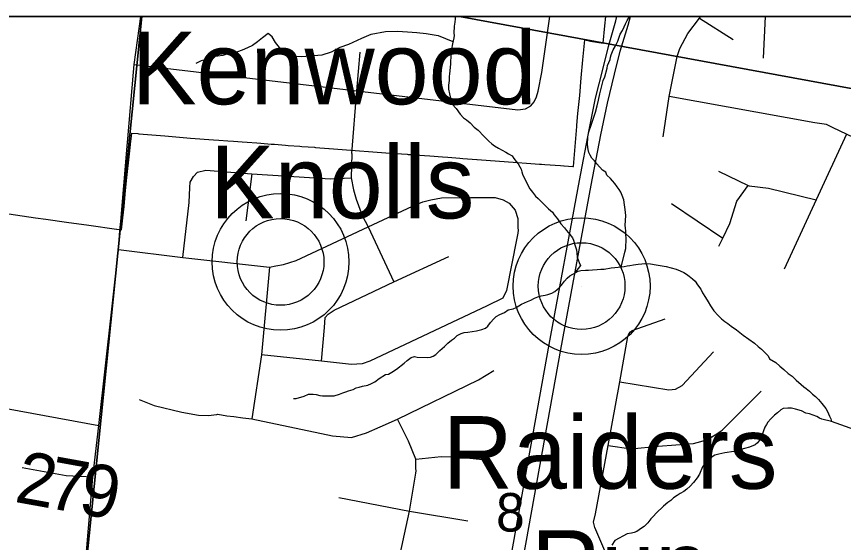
# Model space of a CAD drawing. Extents: x 0 to 34, y 0 to 22.
# Drawn here: x 3.9828 to 4.4325, y 20.6139 to 20.9 of the extents above; entities that cross this region are included whole.
import ezdxf

# ---------------------------------------------------------------- set-up
doc = ezdxf.new("R2010")
doc.units = 0
for name, color, linetype in [('GM_X_City_Street', 7, 'Continuous'), ('GM_X_Corporation', 7, 'Continuous'), ('GM_X_County_Road', 7, 'Continuous'), ('GM_X_County_Road_Text', 7, 'Continuous'), ('GM_X_Interstate_Route', 7, 'Continuous'), ('GM_X_Minor_River', 7, 'Continuous'), ('GM_X_Section_Text', 7, 'Continuous'), ('GM_X_State_Shield', 7, 'Continuous'), ('GM_X_Township_Road', 7, 'Continuous'), ('GM_X_Unincorporated', 7, 'Continuous'), ('GM_X_Unincorporated_Location', 7, 'Continuous'), ('GM_X_Unincorporated_Text', 7, 'Continuous'), ('SH_Cut_Line', 7, 'Continuous'), ('SH_Data', 7, 'Continuous')]:
    doc.layers.add(name, color=color, linetype=linetype)

msp = doc.modelspace()

# ---------------------------------------------------------------- linework, layer by layer
at = {"layer": 'GM_X_City_Street'}
for points in [[(3.97497, 20.79311), (3.9931, 20.79045), (3.99873, 20.78971), (4.01, 20.78813), (4.0222, 20.78643), (4.03714, 20.78434), (4.03742, 20.78431), (4.03996, 20.78396), (4.04066, 20.79041), (4.04135, 20.79658), (4.04194, 20.80341), (4.04288, 20.81241), (4.04404, 20.82359), (4.04486, 20.83042), (4.04489, 20.8307), (4.04547, 20.83631), (4.0455, 20.83652), (4.04872, 20.83628), (4.04928, 20.83623), (4.06345, 20.83516), (4.07747, 20.83391), (4.08992, 20.83297), (4.0928, 20.83275), (4.09776, 20.83238), (4.10075, 20.83215), (4.1056, 20.83179), (4.10816, 20.83159), (4.11343, 20.8312), (4.11574, 20.83103), (4.12127, 20.83061), (4.12303, 20.83048), (4.12911, 20.83002), (4.13058, 20.82991), (4.13695, 20.82943), (4.13796, 20.82936), (4.14479, 20.82884), (4.14541, 20.8288), (4.15262, 20.82826), (4.15281, 20.82824), (4.16228, 20.82753), (4.1646, 20.82735), (4.16701, 20.82717), (4.17654, 20.82645), (4.18597, 20.82574), (4.19531, 20.82503), (4.19573, 20.825), (4.19723, 20.82491), (4.20473, 20.82433), (4.20759, 20.82414), (4.21438, 20.82362), (4.21736, 20.82342), (4.22382, 20.82292), (4.22547, 20.82281), (4.23305, 20.82225), (4.23325, 20.82223), (4.24062, 20.82169), (4.25292, 20.82078), (4.26241, 20.82007), (4.26716, 20.81972), (4.26835, 20.81963), (4.27009, 20.8195), (4.27863, 20.81888), (4.28049, 20.81875), (4.28066, 20.81874), (4.28524, 20.81842), (4.2856, 20.8184), (4.28753, 20.84019), (4.28758, 20.84084), (4.28813, 20.84717), (4.28907, 20.85702), (4.28994, 20.86656), (4.29082, 20.87647), (4.29177, 20.88724), (4.29495, 20.88667), (4.30185, 20.88543), (4.30278, 20.89489), (4.30329, 20.9), (3.92611, 20.9)], [(4.0468, 20.87388), (4.16791, 20.85954), (4.25543, 20.84918), (4.25955, 20.84979), (4.26243, 20.85144), (4.26428, 20.8535), (4.26562, 20.85628), (4.26648, 20.85935), (4.26842, 20.86958), (4.27275, 20.9)], [(4.16509, 20.82548), (4.16791, 20.85954), (4.16966, 20.88069)]]:
    msp.add_lwpolyline(points, dxfattribs=at)
at = {"layer": 'GM_X_Corporation'}
msp.add_lwpolyline([(3.95192, 19.92171), (3.9949, 19.91731), (4.10171, 19.90638), (4.14001, 19.90246), (4.18209, 19.89893), (4.24768, 19.89343), (4.30847, 19.88833), (4.33924, 19.88574), (4.37023, 19.88267), (4.40138, 19.87959), (4.43611, 19.87615), (4.58213, 19.86031), (4.5905, 19.85955), (4.62076, 19.85683), (4.65461, 19.85378), (4.9291, 19.82513), (4.9426, 19.96998), (4.95365, 20.06187), (4.9551, 20.07644), (4.97516, 20.26968), (4.9818, 20.32266), (5.04518, 20.9), (2.1, 20.9)], dxfattribs=at)
at = {"layer": 'GM_X_County_Road'}
for points in [[(4.04329, 20.8335), (4.04635, 20.86978), (4.0468, 20.87388), (4.0504, 20.9)], [(4.03949, 20.78854), (4.04295, 20.82947), (4.04329, 20.8335)], [(4.00194, 20.42555), (4.01183, 20.50815), (4.01801, 20.57463), (4.0243, 20.64932), (4.0275, 20.67758), (4.0382, 20.77323), (4.03907, 20.78354), (4.03949, 20.78854)], [(3.85387, 20.70353), (3.89548, 20.69771), (3.93985, 20.69236), (3.96141, 20.68959), (4.0275, 20.67758)]]:
    msp.add_lwpolyline(points, dxfattribs=at)
at = {"layer": 'GM_X_Interstate_Route'}
for points in [[(4.10569, 20.13725), (4.11588, 20.16239), (4.1222, 20.17847), (4.14304, 20.23011), (4.14895, 20.24368), (4.15849, 20.26868), (4.16744, 20.29065), (4.17662, 20.31368), (4.19256, 20.35667), (4.2032, 20.38903), (4.21618, 20.43357), (4.22309, 20.45994), (4.23291, 20.50351), (4.23513, 20.51628), (4.24925, 20.59234), (4.27239, 20.72152), (4.28895, 20.81079), (4.29422, 20.83832), (4.29772, 20.85553), (4.30167, 20.87122), (4.30474, 20.88372), (4.30862, 20.89772), (4.30932, 20.9)], [(4.14888, 20.22728), (4.1517, 20.23428), (4.16438, 20.26459), (4.17381, 20.28806), (4.18299, 20.31109), (4.19892, 20.35408), (4.20961, 20.38789), (4.22316, 20.43457), (4.23928, 20.50092), (4.24121, 20.51049), (4.25562, 20.58975), (4.27876, 20.71893), (4.29532, 20.8082), (4.30058, 20.83572), (4.30409, 20.85294), (4.30804, 20.86862), (4.31111, 20.88112), (4.31539, 20.89527), (4.31666, 20.9)]]:
    msp.add_lwpolyline(points, dxfattribs=at)
at = {"layer": 'GM_X_Minor_River'}
for points in [[(4.2213, 20.9), (4.22139, 20.89878), (4.22112, 20.89689), (4.22084, 20.89481), (4.22069, 20.89101), (4.22082, 20.88968), (4.22058, 20.88836), (4.21987, 20.88515), (4.21937, 20.88232), (4.21906, 20.87948), (4.21884, 20.87416), (4.21824, 20.86886), (4.21799, 20.86735), (4.21809, 20.86525), (4.21779, 20.8626), (4.2177, 20.86051), (4.21818, 20.85802), (4.21884, 20.85552), (4.21966, 20.85226), (4.22185, 20.84989), (4.22403, 20.84695), (4.22586, 20.84497), (4.22753, 20.84377), (4.22956, 20.84216), (4.23176, 20.83979), (4.23379, 20.83819), (4.23691, 20.83483), (4.2382, 20.83364), (4.23967, 20.83225), (4.24132, 20.83066), (4.24281, 20.82965), (4.24486, 20.82843), (4.24897, 20.82617), (4.25028, 20.82536), (4.25233, 20.82414), (4.25323, 20.82277), (4.2545, 20.8212), (4.25559, 20.81982), (4.25648, 20.81827), (4.25719, 20.81691), (4.25752, 20.81556), (4.25804, 20.81421), (4.25874, 20.81266), (4.25962, 20.81091), (4.26085, 20.8082), (4.26191, 20.80626), (4.26337, 20.80449), (4.265, 20.80233)], [(4.31154, 20.76372), (4.31364, 20.77187), (4.3141, 20.77375), (4.31432, 20.77926), (4.31422, 20.78135), (4.31411, 20.78326), (4.31399, 20.78498), (4.31385, 20.78631), (4.31408, 20.79182), (4.31383, 20.79506), (4.31336, 20.79755), (4.31309, 20.80023), (4.31223, 20.80254), (4.31135, 20.80448), (4.31045, 20.80585), (4.30937, 20.80741), (4.30811, 20.80917), (4.30682, 20.81056), (4.30573, 20.81193), (4.3039, 20.81372), (4.3032, 20.81527), (4.30153, 20.81647), (4.29841, 20.81983), (4.29714, 20.8214), (4.29568, 20.82298), (4.29479, 20.82454), (4.29408, 20.82609), (4.29358, 20.82763), (4.2933, 20.8303), (4.29348, 20.83448), (4.29398, 20.83731), (4.29527, 20.84088), (4.29679, 20.84519), (4.29767, 20.84801), (4.29857, 20.8514), (4.29927, 20.85441), (4.29999, 20.85799), (4.30182, 20.86515), (4.30267, 20.86721), (4.30401, 20.87191), (4.30426, 20.87342), (4.30554, 20.8766), (4.30579, 20.87792), (4.30622, 20.87924), (4.30729, 20.88186), (4.30832, 20.88372), (4.30977, 20.88651), (4.31108, 20.89046), (4.31231, 20.89231), (4.31316, 20.89437), (4.31399, 20.89604), (4.31483, 20.89791), (4.31608, 20.9)], [(4.13106, 20.87863), (4.13801, 20.87833), (4.14428, 20.87878), (4.14904, 20.87907), (4.15402, 20.88088), (4.15881, 20.88326), (4.1636, 20.88488), (4.1705, 20.88817), (4.17568, 20.89035), (4.1835, 20.89191), (4.18996, 20.89198), (4.19546, 20.89168), (4.20058, 20.89139), (4.20551, 20.89073), (4.21214, 20.88965), (4.22016, 20.88647)], [(4.13106, 20.87863), (4.12772, 20.88047), (4.12574, 20.88322), (4.12356, 20.88578), (4.12178, 20.88889), (4.11957, 20.8907), (4.11663, 20.88835), (4.11388, 20.88618), (4.11114, 20.8842), (4.10844, 20.88299), (4.10554, 20.88178), (4.10303, 20.88074), (4.10072, 20.88007), (4.09824, 20.8798), (4.09497, 20.87879), (4.0923, 20.87852), (4.08981, 20.87806), (4.08634, 20.87668), (4.08326, 20.87586), (4.08036, 20.87446)], [(4.265, 20.80233), (4.26647, 20.80094), (4.26776, 20.79975), (4.26978, 20.79777), (4.27217, 20.79539), (4.2742, 20.7936), (4.27509, 20.79204), (4.27691, 20.78988), (4.27871, 20.78714), (4.28072, 20.78497), (4.28181, 20.78359), (4.28364, 20.78143), (4.28509, 20.77966), (4.28561, 20.77831), (4.28646, 20.7758), (4.28731, 20.77311), (4.28743, 20.77139), (4.28772, 20.7691), (4.28874, 20.7662), (4.28943, 20.76446), (4.28623, 20.7604)], [(4.13351, 20.69213), (4.13486, 20.69227), (4.1393, 20.69342), (4.14164, 20.69447), (4.14413, 20.69456), (4.14584, 20.6943), (4.14773, 20.69384), (4.14925, 20.69359), (4.15136, 20.6937), (4.15365, 20.69361), (4.15556, 20.69372), (4.15847, 20.69456), (4.16021, 20.69525), (4.16196, 20.69575), (4.16331, 20.69627), (4.16584, 20.69712), (4.16759, 20.698), (4.16913, 20.69832), (4.17088, 20.69882), (4.17377, 20.69946), (4.17591, 20.70033), (4.17766, 20.70121), (4.18003, 20.70302), (4.18337, 20.70517), (4.18511, 20.70548), (4.18687, 20.70655), (4.18942, 20.70816), (4.19357, 20.71142), (4.19516, 20.71288), (4.19733, 20.7145), (4.19926, 20.71499), (4.20059, 20.71475), (4.20632, 20.71452), (4.20785, 20.71465), (4.2094, 20.71516), (4.21078, 20.71606), (4.21297, 20.71825), (4.21555, 20.72043), (4.21734, 20.72226), (4.21932, 20.72389), (4.22089, 20.72497), (4.22248, 20.72643), (4.22463, 20.72749), (4.22618, 20.728), (4.2283, 20.72829), (4.2306, 20.72858), (4.23292, 20.72906), (4.23581, 20.7297), (4.23775, 20.73039), (4.23913, 20.73147), (4.24056, 20.73351), (4.24236, 20.73553), (4.24356, 20.73681), (4.24571, 20.73787), (4.24823, 20.73891), (4.2502, 20.74035), (4.25291, 20.741), (4.25447, 20.7417), (4.25741, 20.74349), (4.26071, 20.74488), (4.26247, 20.74576), (4.26443, 20.74682), (4.26637, 20.7475), (4.26811, 20.74801), (4.27023, 20.74849), (4.27177, 20.74881), (4.2739, 20.74949), (4.27547, 20.75038), (4.27805, 20.75256), (4.27966, 20.75458), (4.28087, 20.75606), (4.28227, 20.75771), (4.28366, 20.75899), (4.28816, 20.76147), (4.28971, 20.76179), (4.2922, 20.76207), (4.29392, 20.762), (4.29603, 20.76211), (4.29852, 20.76239), (4.30063, 20.7625), (4.30236, 20.76262), (4.30621, 20.76322), (4.31196, 20.76376), (4.31331, 20.76408), (4.31486, 20.7644), (4.31639, 20.76453), (4.31832, 20.76483), (4.32082, 20.7653), (4.32293, 20.76541), (4.32427, 20.76555), (4.32752, 20.76542), (4.33055, 20.76492), (4.33606, 20.76394), (4.34154, 20.76258), (4.34361, 20.76173), (4.34567, 20.7607), (4.34717, 20.75988), (4.34865, 20.75868), (4.35031, 20.75728), (4.35179, 20.75608), (4.35304, 20.75394)], [(4.35304, 20.75394), (4.35485, 20.75159), (4.35592, 20.74964), (4.35754, 20.74711), (4.35897, 20.74477), (4.36022, 20.74262), (4.36202, 20.73989), (4.3644, 20.73732), (4.36623, 20.73554), (4.3679, 20.73414), (4.36957, 20.73293), (4.37142, 20.73153), (4.37439, 20.72951), (4.37791, 20.7267), (4.38107, 20.72449), (4.38404, 20.72228), (4.38607, 20.72048), (4.38792, 20.71908), (4.3892, 20.7177), (4.39159, 20.71532), (4.39229, 20.71377), (4.39564, 20.71173), (4.39786, 20.70974), (4.40008, 20.70794), (4.40247, 20.70576), (4.40452, 20.70434), (4.40672, 20.70216), (4.40949, 20.69977), (4.41097, 20.69857), (4.41226, 20.69757), (4.41393, 20.69617), (4.41558, 20.69458), (4.41724, 20.69319), (4.4189, 20.6916), (4.42072, 20.68943), (4.4229, 20.68668), (4.42379, 20.68513), (4.42484, 20.68261), (4.42554, 20.68106), (4.426, 20.67966)], [(4.426, 20.67966), (4.42075, 20.68088), (4.41944, 20.6815), (4.41794, 20.68232), (4.41399, 20.68381), (4.4121, 20.68426), (4.40966, 20.6855), (4.40645, 20.68639), (4.40417, 20.68686), (4.40227, 20.68694), (4.39977, 20.68666), (4.3984, 20.68595), (4.39661, 20.68431), (4.39503, 20.68304), (4.39304, 20.68103), (4.39144, 20.67938), (4.39062, 20.67808), (4.3898, 20.67659), (4.38895, 20.67453), (4.38807, 20.67191), (4.38682, 20.66948), (4.38581, 20.668), (4.38443, 20.66692), (4.38132, 20.66571), (4.37861, 20.66506), (4.37281, 20.66339), (4.368, 20.66263), (4.36472, 20.66181), (4.36259, 20.66132), (4.36063, 20.66007), (4.35885, 20.65862), (4.35744, 20.65696), (4.35583, 20.65493), (4.35414, 20.65101), (4.35291, 20.64896), (4.3509, 20.64657), (4.34909, 20.64455), (4.3473, 20.64291), (4.34572, 20.64164), (4.34377, 20.64058), (4.34199, 20.63932), (4.34003, 20.63807), (4.33863, 20.6366), (4.33706, 20.63552), (4.33468, 20.63352), (4.33071, 20.62988), (4.32911, 20.62823), (4.32771, 20.62677), (4.32609, 20.62455), (4.32409, 20.62254), (4.32272, 20.62164), (4.32016, 20.61984), (4.31861, 20.61933), (4.31726, 20.619), (4.31494, 20.61853), (4.30811, 20.61499), (4.30647, 20.6124)], [(4.47522, 20.66216), (4.426, 20.67966)]]:
    msp.add_lwpolyline(points, dxfattribs=at)
at = {"layer": 'GM_X_State_Shield'}
for points in [[(4.05097, 20.9), (3.52038, 20.9), (3.4808, 20.49635), (4.00293, 20.42622)], [(4.22367, 20.9), (4.05097, 20.9), (4.00293, 20.42622), (4.48038, 20.34556), (4.52837, 20.84401)], [(4.53365, 20.9), (4.22367, 20.9), (4.52837, 20.84401)]]:
    msp.add_lwpolyline(points, close=True, dxfattribs=at)
at = {"layer": 'GM_X_Township_Road'}
for p, q in [((4.38906, 20.87741), (4.3901, 20.9)), ((4.35413, 20.89914), (4.37259, 20.88756)), ((4.11078, 20.81444), (4.10746, 20.78886)), ((4.33899, 20.7983), (4.36692, 20.77946)), ((4.00975, 20.65018), (3.98583, 20.65444)), ((4.0243, 20.64932), (4.00975, 20.65018))]:
    msp.add_line(p, q, dxfattribs=at)
for points in [[(4.33453, 20.83463), (4.33772, 20.85641), (4.34205, 20.87826), (4.34342, 20.88259), (4.34777, 20.89075), (4.35413, 20.89914), (4.35482, 20.9)], [(4.58909, 20.78396), (4.52096, 20.79718), (4.51644, 20.79824), (4.51172, 20.79994), (4.49863, 20.80803), (4.48144, 20.81889), (4.47456, 20.82286), (4.46606, 20.82576), (4.45448, 20.82754), (4.4459, 20.83041), (4.43408, 20.83605), (4.42696, 20.83944), (4.42322, 20.84125), (4.41697, 20.84216), (4.33772, 20.85641)], [(4.43408, 20.83605), (4.41768, 20.80035), (4.40032, 20.76255)], [(4.16509, 20.82548), (4.16483, 20.81233), (4.16604, 20.80571), (4.16744, 20.8006), (4.17075, 20.79177), (4.17406, 20.78566), (4.188, 20.75568)], [(4.07328, 20.76881), (4.07669, 20.7988), (4.07699, 20.80692), (4.07729, 20.80982), (4.07903, 20.81294), (4.0813, 20.81524), (4.08571, 20.81634), (4.11078, 20.81444), (4.1536, 20.81163), (4.16483, 20.81233)], [(4.36449, 20.81591), (4.38064, 20.80815), (4.38117, 20.80789), (4.39177, 20.80667), (4.41768, 20.80035)], [(4.36477, 20.77503), (4.36692, 20.77946), (4.37078, 20.78743), (4.37451, 20.7995), (4.38064, 20.80815)], [(4.0382, 20.77323), (4.07328, 20.76881), (4.12041, 20.7636), (4.12382, 20.7644), (4.12803, 20.7651), (4.13495, 20.76721), (4.17406, 20.78566), (4.19823, 20.79689), (4.20374, 20.7992), (4.20805, 20.8003), (4.21387, 20.8014), (4.22971, 20.8016), (4.24315, 20.8016), (4.24736, 20.8003), (4.25067, 20.79839), (4.25398, 20.79458), (4.25549, 20.79007), (4.25539, 20.78497), (4.25553, 20.78373), (4.25543, 20.78217), (4.25493, 20.77938), (4.24928, 20.75087), (4.24724, 20.74679), (4.2388, 20.74257), (4.17486, 20.71246), (4.17085, 20.71105), (4.16503, 20.71065), (4.14859, 20.71256), (4.116, 20.71596)], [(4.14859, 20.71256), (4.1503, 20.73079), (4.15059, 20.73632), (4.1522, 20.73812), (4.15551, 20.74033), (4.188, 20.75568), (4.21788, 20.76951)], [(4.12041, 20.7636), (4.116, 20.71596), (4.11078, 20.68107)], [(4.43185, 20.51237), (4.42256, 20.51581), (4.41371, 20.52061), (4.38034, 20.53932), (4.37528, 20.54109), (4.36947, 20.5421), (4.35594, 20.54248), (4.35215, 20.54362), (4.34485, 20.54805), (4.32611, 20.55967), (4.32257, 20.56359), (4.31941, 20.57042), (4.29726, 20.62198), (4.29658, 20.62486), (4.29764, 20.62939), (4.30447, 20.66669), (4.3108, 20.70133), (4.3153, 20.72589), (4.31579, 20.72733), (4.31662, 20.7285), (4.31766, 20.72926), (4.33547, 20.73547)], [(4.3108, 20.70133), (4.33748, 20.69697), (4.34109, 20.69728), (4.34474, 20.69931), (4.36178, 20.71763)], [(4.18064, 20.67679), (4.19, 20.68097), (4.23405, 20.70228), (4.24228, 20.70735)], [(4.30447, 20.66669), (4.31713, 20.66484), (4.33167, 20.66624), (4.35088, 20.66775), (4.35822, 20.66977), (4.36264, 20.67243), (4.36656, 20.67496), (4.3878, 20.69614)], [(4.0495, 20.69159), (4.05768, 20.68845), (4.07277, 20.68468), (4.0818, 20.68307), (4.08702, 20.68297), (4.09176, 20.68352)], [(4.09176, 20.68352), (4.09223, 20.68357), (4.09724, 20.68277), (4.10105, 20.68237), (4.10592, 20.68172)], [(4.10592, 20.68172), (4.11078, 20.68107), (4.15471, 20.67194), (4.16493, 20.67094), (4.17315, 20.67345), (4.18064, 20.67679)], [(4.1897, 20.59916), (4.19648, 20.63084), (4.20003, 20.65162), (4.20011, 20.65286), (4.19996, 20.65403), (4.20003, 20.6591), (4.19602, 20.66903), (4.19, 20.68097)], [(4.20003, 20.6591), (4.21367, 20.66071), (4.2241, 20.66021), (4.23796, 20.65874)], [(4.15801, 20.63825), (4.19648, 20.63084), (4.22821, 20.62561)]]:
    msp.add_lwpolyline(points, dxfattribs=at)
at = {"layer": 'GM_X_Unincorporated'}
for centre, radius in [((4.12639, 20.76649), 0.0372), ((4.12639, 20.76649), 0.02358), ((4.29011, 20.75335), 0.0372), ((4.29011, 20.75335), 0.02358)]:
    msp.add_circle(centre, radius, dxfattribs=at)
at = {"layer": 'GM_X_Unincorporated_Location'}
for p, q in [((4.12639, 20.76649), (4.12639, 20.76649)), ((4.29011, 20.75335), (4.29011, 20.75335))]:
    msp.add_line(p, q, dxfattribs=at)
at = {"layer": 'SH_Cut_Line'}
msp.add_lwpolyline([(5.67696, 20.9), (2.1, 20.9), (2.1, 17.35231)], dxfattribs=at)
at = {"layer": 'SH_Data'}
msp.add_line((2.1, 20.9), (8.9, 20.9), dxfattribs=at)

# ---------------------------------------------------------------- texts
at = {"layer": 'GM_X_County_Road_Text'}
for s, rotation, p in [('2', 349.7336, (3.98113, 20.63606)), ('7', 349.7572, (3.99836, 20.63293)), ('9', 349.7697, (4.01559, 20.62982))]:
    msp.add_text(s, height=0.02841, rotation=rotation, dxfattribs=at).set_placement(p)
at = {"layer": 'GM_X_Section_Text'}
msp.add_text('8', height=0.02093, rotation=0, dxfattribs=at).set_placement((4.24358, 20.61981))
at = {"layer": 'GM_X_Unincorporated_Text'}
for s, p in [('Kenwood', (4.04546, 20.85226)), ('Knolls', (4.08796, 20.79018)), ('Raiders', (4.21462, 20.64309)), ('Run', (4.26254, 20.58101))]:
    msp.add_text(s, height=0.039489, rotation=0, dxfattribs=at).set_placement(p)

doc.saveas('drawing.dxf')
